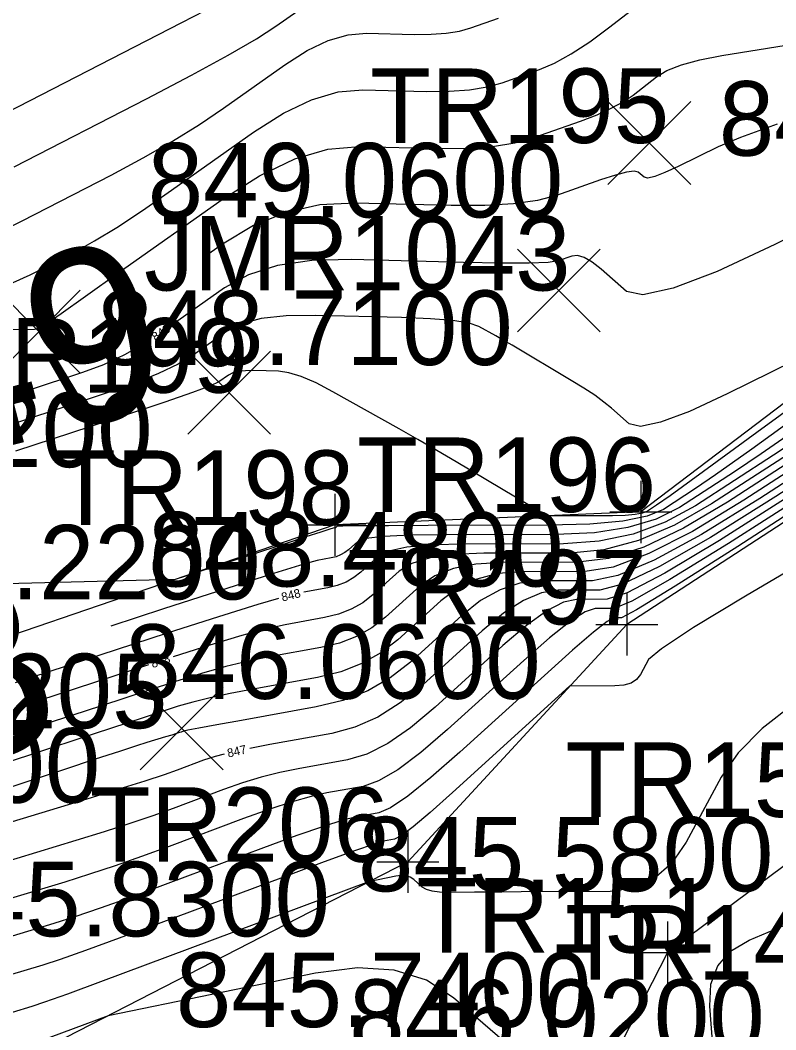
# Model space of a CAD drawing. Extents: x 1654928 to 1810050, y 486881 to 626330.
# Drawn here: x 1801367.8 to 1801379.97, y 489789.91 to 489806.17 of the extents above; entities that cross this region are included whole.
import ezdxf

# ---------------------------------------------------------------- set-up
doc = ezdxf.new("R2010")
doc.units = 0
for name, color, linetype in [('DR_X_Ditch', 7, 'Continuous'), ('DT_X_Contour_Major', 7, 'Continuous'), ('DT_X_Contour_Minor', 7, 'Continuous'), ('SV_X_Random_Point', 7, 'Continuous'), ('SV_X_Shot_Marker', 7, 'Continuous'), ('SV_X_Text_Elevation', 7, 'Continuous'), ('SV_X_Text_Name', 7, 'Continuous'), ('SV_X_Toe_of_Slope', 7, 'Continuous'), ('SV_X_Top_of_Bank', 7, 'Continuous')]:
    doc.layers.add(name, color=color, linetype=linetype)

msp = doc.modelspace()

# ---------------------------------------------------------------- linework, layer by layer
at = {"layer": 'DR_X_Ditch'}
msp.add_lwpolyline([(1801415.613, 489805.461), (1801399.12, 489798.656), (1801394.115, 489798.231), (1801381.169, 489793.34), (1801378.227, 489791.154), (1801376.864, 489788.486), (1801373.817, 489786.687), (1801350.547, 489785.463), (1801345.905, 489787.547), (1801327.981, 489787.847), (1801322.506, 489787.279)], dxfattribs=at)
at = {"layer": 'DT_X_Contour_Major'}
for points in [[(1801367.576, 489804.681), (1801370.403, 489806.138), (1801371.345, 489806.626)], [(1801379.993, 489804.497), (1801379.402, 489804.284), (1801379.044, 489804.134), (1801378.403, 489803.818), (1801378.188, 489803.718), (1801378.024, 489803.655), (1801377.912, 489803.63), (1801377.851, 489803.643), (1801377.756, 489803.726), (1801377.692, 489803.741), (1801377.57, 489803.725), (1801377.39, 489803.678), (1801377.152, 489803.599), (1801376.44, 489803.348), (1801376.134, 489803.267), (1801375.75, 489803.213), (1801375.287, 489803.187), (1801374.746, 489803.188), (1801373.199, 489803.228), (1801372.63, 489803.197), (1801372.084, 489803.076), (1801371.56, 489802.865), (1801371.059, 489802.563), (1801370.751, 489802.345)], [(1801382.452, 489800.238), (1801379.714, 489798.47), (1801378.776, 489797.89), (1801378.014, 489797.475), (1801377.429, 489797.226), (1801377.02, 489797.142), (1801376.166, 489797.14), (1801375.848, 489797.104), (1801375.532, 489796.998), (1801375.219, 489796.823), (1801374.909, 489796.578), (1801374.087, 489795.832), (1801373.76, 489795.577), (1801373.399, 489795.371), (1801373.001, 489795.216), (1801372.568, 489795.11), (1801371.365, 489794.894), (1801370.969, 489794.822), (1801370.681, 489794.769), (1801370.503, 489794.735), (1801370.434, 489794.721), (1801370.395, 489794.706), (1801370.369, 489794.697), (1801370.318, 489794.681), (1801370.242, 489794.658), (1801370.142, 489794.627), (1801369.844, 489794.536), (1801369.676, 489794.483), (1801369.399, 489794.394), (1801369.012, 489794.267), (1801368.514, 489794.103), (1801367.041, 489793.617)], [(1801380.363, 489799.623), (1801379.739, 489799.185), (1801379.309, 489798.896), (1801378.421, 489798.322), (1801378.047, 489798.134), (1801377.591, 489797.999), (1801377.053, 489797.917), (1801376.434, 489797.888), (1801374.671, 489797.883), (1801374.086, 489797.875), (1801373.652, 489797.854), (1801373.37, 489797.822), (1801373.238, 489797.778), (1801373.09, 489797.643), (1801373.031, 489797.597), (1801372.964, 489797.56), (1801372.891, 489797.531), (1801372.811, 489797.512), (1801372.586, 489797.472), (1801372.369, 489797.411), (1801371.883, 489797.261), (1801371.131, 489797.02), (1801370.111, 489796.689), (1801369.261, 489796.412)], [(1801380.633, 489797.57), (1801379.484, 489796.895), (1801378.65, 489796.388), (1801378.13, 489796.047), (1801377.923, 489795.873), (1801377.793, 489795.631), (1801377.73, 489795.552), (1801377.641, 489795.495), (1801377.525, 489795.46), (1801377.382, 489795.448), (1801376.652, 489795.443), (1801374.768, 489793.734), (1801374.407, 489793.412), (1801374.13, 489793.179), (1801373.938, 489793.034), (1801373.83, 489792.978), (1801373.655, 489792.947), (1801373.505, 489792.902), (1801373.187, 489792.791), (1801372.699, 489792.614), (1801372.044, 489792.371), (1801370.069, 489791.634), (1801369.395, 489791.384), (1801368.854, 489791.187), (1801368.445, 489791.044), (1801368.169, 489790.953), (1801367.609, 489790.783)]]:
    msp.add_lwpolyline(points, dxfattribs=at)
at = {"layer": 'DT_X_Contour_Minor'}
for points in [[(1801367.687, 489801.947), (1801367.965, 489802.071), (1801368.698, 489802.448), (1801369, 489802.616), (1801369.358, 489802.836), (1801369.771, 489803.109), (1801370.238, 489803.433), (1801371.56, 489804.369), (1801372.041, 489804.675), (1801372.495, 489804.891), (1801372.922, 489805.017), (1801373.321, 489805.052), (1801374.348, 489805.026), (1801374.713, 489805.027), (1801375.038, 489805.051), (1801375.323, 489805.097), (1801375.568, 489805.165), (1801376.169, 489805.378), (1801376.408, 489805.481), (1801376.677, 489805.63), (1801376.975, 489805.826), (1801377.301, 489806.068), (1801378.211, 489806.777)], [(1801367.706, 489803.811), (1801369.835, 489804.908), (1801370.564, 489805.289), (1801371.154, 489805.611), (1801371.607, 489805.874), (1801371.92, 489806.077), (1801372.573, 489806.539)], [(1801367.339, 489802.699), (1801367.835, 489802.941), (1801369.266, 489803.678), (1801369.782, 489803.953), (1801370.256, 489804.224), (1801370.689, 489804.491), (1801371.079, 489804.755), (1801372.066, 489805.454), (1801372.426, 489805.683), (1801372.765, 489805.844), (1801373.083, 489805.938), (1801373.381, 489805.964), (1801374.148, 489805.944), (1801374.421, 489805.945), (1801374.664, 489805.963), (1801374.877, 489805.997), (1801375.06, 489806.049), (1801375.508, 489806.207)], [(1801367.634, 489801.194), (1801367.881, 489801.193), (1801368.035, 489801.195), (1801368.095, 489801.2), (1801368.13, 489801.218), (1801368.46, 489801.448), (1801368.853, 489801.726), (1801369.397, 489802.112), (1801371.053, 489803.285), (1801371.657, 489803.668), (1801372.226, 489803.938), (1801372.76, 489804.096), (1801373.26, 489804.14), (1801374.547, 489804.107), (1801375.004, 489804.109), (1801375.412, 489804.138), (1801375.769, 489804.196), (1801376.076, 489804.282), (1801376.829, 489804.548), (1801377.094, 489804.649), (1801377.323, 489804.753), (1801377.516, 489804.858), (1801377.674, 489804.967), (1801378.049, 489805.258), (1801378.22, 489805.362), (1801378.454, 489805.454), (1801378.749, 489805.533), (1801379.106, 489805.602), (1801380.142, 489805.768)], [(1801382.74, 489803.929), (1801379.96, 489802.558), (1801379.029, 489802.126), (1801378.32, 489801.855), (1801377.833, 489801.747), (1801377.568, 489801.801), (1801377.159, 489802.16), (1801377.015, 489802.275), (1801376.888, 489802.348), (1801376.779, 489802.381), (1801376.687, 489802.372), (1801376.466, 489802.294), (1801376.309, 489802.27), (1801376.003, 489802.258), (1801375.549, 489802.258), (1801374.945, 489802.27), (1801373.138, 489802.316), (1801372.502, 489802.3), (1801371.949, 489802.219), (1801371.479, 489802.072), (1801371.091, 489801.86), (1801370.248, 489801.263)], [(1801382.372, 489801.721), (1801379.192, 489800.153), (1801378.582, 489799.871), (1801378.115, 489799.696), (1801377.793, 489799.63), (1801377.613, 489799.67), (1801377.326, 489799.923), (1801377.205, 489800.022), (1801377.056, 489800.13), (1801376.881, 489800.246), (1801376.678, 489800.37), (1801375.725, 489800.936), (1801375.579, 489801.02), (1801375.462, 489801.086), (1801375.187, 489801.24), (1801375.032, 489801.292), (1801374.773, 489801.333), (1801374.411, 489801.363), (1801373.945, 489801.382), (1801372.563, 489801.417), (1801372.085, 489801.411), (1801371.686, 489801.365), (1801371.365, 489801.281), (1801371.124, 489801.157), (1801370.586, 489800.776), (1801370.346, 489800.63), (1801370.03, 489800.479), (1801369.638, 489800.321), (1801369.17, 489800.158), (1801367.821, 489799.716), (1801367.371, 489799.572)], [(1801369.9, 489801.028), (1801369.824, 489800.978), (1801369.482, 489800.784), (1801369.144, 489800.623), (1801368.808, 489800.497), (1801367.916, 489800.205), (1801367.619, 489800.109)], [(1801380.853, 489800.396), (1801379.669, 489799.531), (1801378.808, 489798.904), (1801378.269, 489798.513), (1801378.052, 489798.358), (1801377.904, 489798.263), (1801377.827, 489798.231), (1801377.708, 489798.209), (1801377.545, 489798.195), (1801377.34, 489798.19), (1801376.284, 489798.187), (1801374.822, 489799.057), (1801374.512, 489799.24), (1801374.207, 489799.417), (1801373.908, 489799.589), (1801372.84, 489800.187), (1801372.567, 489800.329), (1801372.33, 489800.432), (1801372.128, 489800.495), (1801371.962, 489800.519), (1801371.568, 489800.529), (1801371.431, 489800.527), (1801371.317, 489800.514), (1801371.225, 489800.49), (1801371.156, 489800.455), (1801371.003, 489800.346), (1801370.868, 489800.282), (1801370.578, 489800.173), (1801370.133, 489800.019), (1801369.533, 489799.82), (1801367.726, 489799.228)], [(1801383.081, 489800.507), (1801379.973, 489798.5), (1801378.922, 489797.841), (1801378.099, 489797.371), (1801377.504, 489797.088), (1801377.138, 489796.993), (1801376.465, 489796.991), (1801376.2, 489796.95), (1801375.908, 489796.827), (1801375.589, 489796.623), (1801375.243, 489796.338), (1801374.286, 489795.469), (1801373.925, 489795.176), (1801373.561, 489794.947), (1801373.192, 489794.783), (1801372.82, 489794.684), (1801371.823, 489794.504), (1801371.5, 489794.443)], [(1801381.824, 489799.97), (1801379.456, 489798.441), (1801378.63, 489797.939), (1801377.929, 489797.58), (1801377.354, 489797.364), (1801376.903, 489797.291), (1801375.867, 489797.288), (1801375.495, 489797.258), (1801375.156, 489797.17), (1801374.849, 489797.023), (1801374.575, 489796.818), (1801373.887, 489796.194), (1801373.613, 489795.981), (1801373.306, 489795.808), (1801372.965, 489795.676), (1801372.592, 489795.586), (1801371.552, 489795.399), (1801371.184, 489795.329), (1801370.861, 489795.259), (1801370.583, 489795.19), (1801370.349, 489795.121), (1801369.784, 489794.936), (1801368.747, 489794.596), (1801368.224, 489794.423), (1801366.71, 489793.924)], [(1801380.425, 489799.871), (1801379.585, 489799.263), (1801379.004, 489798.849), (1801378.681, 489798.627), (1801378.163, 489798.292), (1801377.902, 489798.182), (1801377.507, 489798.103), (1801376.978, 489798.055), (1801376.316, 489798.037), (1801374.372, 489798.031), (1801373.734, 489798.029), (1801373.276, 489798.026), (1801373, 489798.022), (1801372.904, 489798.018), (1801372.891, 489798.005), (1801372.885, 489798.001), (1801372.879, 489797.998), (1801372.873, 489797.995), (1801372.865, 489797.993), (1801372.845, 489797.99), (1801372.791, 489797.973), (1801372.643, 489797.926), (1801372.403, 489797.848), (1801372.069, 489797.739), (1801370.296, 489797.161), (1801366.727, 489797.07)], [(1801381.195, 489799.701), (1801379.197, 489798.411), (1801378.484, 489797.988), (1801377.845, 489797.685), (1801377.279, 489797.502), (1801376.786, 489797.441), (1801375.568, 489797.437), (1801375.143, 489797.412), (1801374.78, 489797.341), (1801374.479, 489797.223), (1801374.241, 489797.058), (1801373.688, 489796.556), (1801373.467, 489796.385), (1801373.22, 489796.246), (1801372.947, 489796.14), (1801372.647, 489796.067), (1801371.811, 489795.917), (1801371.48, 489795.85), (1801371.117, 489795.76), (1801370.72, 489795.647), (1801370.289, 489795.513), (1801369.096, 489795.124), (1801368.649, 489794.978), (1801368.201, 489794.831), (1801368.18, 489794.824)], [(1801380.567, 489799.433), (1801378.938, 489798.381), (1801378.339, 489798.036), (1801377.76, 489797.789), (1801377.204, 489797.64), (1801376.668, 489797.59), (1801375.269, 489797.585), (1801374.791, 489797.566), (1801374.404, 489797.512), (1801374.109, 489797.422), (1801373.907, 489797.298), (1801373.489, 489796.919), (1801373.322, 489796.789), (1801373.135, 489796.684), (1801372.928, 489796.604), (1801372.701, 489796.549), (1801372.069, 489796.435), (1801371.776, 489796.37), (1801371.372, 489796.26), (1801370.857, 489796.105), (1801370.266, 489795.916)], [(1801380.474, 489799.521), (1801379.938, 489799.164), (1801378.68, 489798.352), (1801378.193, 489798.085), (1801377.676, 489797.894), (1801377.128, 489797.779), (1801376.551, 489797.739), (1801374.97, 489797.734), (1801374.438, 489797.72), (1801374.028, 489797.683), (1801373.739, 489797.622), (1801373.572, 489797.538), (1801373.289, 489797.281), (1801373.176, 489797.193), (1801373.05, 489797.122), (1801372.91, 489797.068), (1801372.756, 489797.03), (1801372.371, 489796.961)], [(1801380.749, 489798.589), (1801379.359, 489797.695), (1801378.352, 489797.057), (1801377.729, 489796.674), (1801377.49, 489796.546), (1801377.362, 489796.545), (1801377.257, 489796.487), (1801377.036, 489796.313), (1801376.699, 489796.024), (1801376.246, 489795.618), (1801374.884, 489794.383), (1801374.419, 489793.974), (1801374.047, 489793.675), (1801373.766, 489793.485), (1801373.577, 489793.405), (1801373.197, 489793.336), (1801372.998, 489793.286), (1801372.686, 489793.187), (1801372.26, 489793.038), (1801371.722, 489792.841), (1801370.135, 489792.248), (1801369.577, 489792.042), (1801369.092, 489791.869), (1801368.682, 489791.729), (1801368.346, 489791.622), (1801367.548, 489791.378)], [(1801380.232, 489798.53), (1801379.067, 489797.793), (1801378.183, 489797.266), (1801377.579, 489796.95), (1801377.255, 489796.844), (1801376.764, 489796.843), (1801376.552, 489796.796), (1801376.284, 489796.656), (1801375.959, 489796.423), (1801375.577, 489796.098), (1801374.485, 489795.107), (1801374.09, 489794.775), (1801373.723, 489794.523), (1801373.384, 489794.35), (1801373.073, 489794.257), (1801372.281, 489794.115), (1801371.983, 489794.054), (1801371.684, 489793.978), (1801371.382, 489793.887), (1801371.078, 489793.781), (1801370.265, 489793.477), (1801369.939, 489793.359), (1801369.569, 489793.234), (1801369.156, 489793.1), (1801368.7, 489792.958), (1801367.426, 489792.57)], [(1801380.49, 489798.559), (1801379.213, 489797.744), (1801378.268, 489797.161), (1801377.654, 489796.812), (1801377.372, 489796.695), (1801377.063, 489796.694), (1801376.905, 489796.641), (1801376.66, 489796.485), (1801376.329, 489796.224), (1801375.912, 489795.858), (1801374.685, 489794.745), (1801374.255, 489794.375), (1801373.885, 489794.099), (1801373.575, 489793.918), (1801373.325, 489793.831), (1801372.739, 489793.726), (1801372.491, 489793.67), (1801372.185, 489793.582), (1801371.821, 489793.463), (1801371.4, 489793.311), (1801370.2, 489792.863), (1801369.758, 489792.701), (1801369.331, 489792.552), (1801368.919, 489792.415), (1801368.523, 489792.29), (1801367.487, 489791.974)], [(1801371.964, 489796.859), (1801371.628, 489796.76), (1801370.994, 489796.563), (1801370.17, 489796.297), (1801367.722, 489795.499)], [(1801369.867, 489795.787), (1801368.409, 489795.311), (1801367.771, 489795.103)], [(1801380.263, 489795.159), (1801379.756, 489794.764), (1801379.367, 489794.37), (1801379.095, 489793.977), (1801378.529, 489792.93), (1801378.293, 489792.587), (1801378.01, 489792.34), (1801377.681, 489792.192), (1801377.304, 489792.14), (1801375.869, 489792.131), (1801375.559, 489792.129), (1801375.122, 489792.126), (1801374.7, 489792.123), (1801374.554, 489792.127), (1801374.436, 489792.143), (1801374.344, 489792.171), (1801374.279, 489792.21), (1801374.141, 489792.33), (1801374.084, 489792.367), (1801374.016, 489792.388), (1801373.939, 489792.393), (1801373.85, 489792.382), (1801373.415, 489792.293), (1801369.093, 489790.68), (1801368.562, 489790.485), (1801368.195, 489790.353), (1801367.992, 489790.285), (1801367.671, 489790.187)], [(1801371.09, 489794.35), (1801370.942, 489794.311), (1801370.756, 489794.251), (1801370.33, 489794.092), (1801370.12, 489794.018), (1801369.807, 489793.916), (1801369.393, 489793.785), (1801368.877, 489793.627), (1801367.364, 489793.166)], [(1801379.032, 489788.659), (1801378.909, 489790.293), (1801378.927, 489790.647), (1801379.039, 489790.942), (1801379.244, 489791.177), (1801379.542, 489791.352), (1801380.464, 489791.74)], [(1801375.843, 489789.506), (1801374.783, 489790.427), (1801374.345, 489790.711), (1801373.828, 489790.871), (1801373.233, 489790.909), (1801372.557, 489790.823), (1801369.221, 489790.137), (1801368.281, 489789.786)]]:
    msp.add_lwpolyline(points, dxfattribs=at)
at = {"layer": 'SV_X_Random_Point'}
for p, q in [((1801377.269, 489803.528), (1801378.602, 489804.863)), ((1801377.269, 489804.863), (1801378.602, 489803.528)), ((1801375.811, 489801.152), (1801377.145, 489802.487)), ((1801375.811, 489802.487), (1801377.145, 489801.152)), ((1801367.434, 489800.489), (1801368.768, 489801.824)), ((1801367.434, 489801.824), (1801368.768, 489800.489)), ((1801370.503, 489799.506), (1801371.836, 489800.841)), ((1801370.503, 489800.841), (1801371.836, 489799.506)), ((1801369.735, 489794.1), (1801371.069, 489795.435)), ((1801369.735, 489795.435), (1801371.069, 489794.1))]:
    msp.add_line(p, q, dxfattribs=at)
at = {"layer": 'SV_X_Shot_Marker'}
for p, q in [((1801377.801, 489798.751), (1801377.801, 489797.751)), ((1801372.871, 489798.542), (1801372.871, 489797.542)), ((1801377.301, 489798.251), (1801378.301, 489798.251)), ((1801377.801, 489798.251), (1801377.801, 489798.251)), ((1801372.371, 489798.042), (1801373.371, 489798.042)), ((1801372.871, 489798.042), (1801372.871, 489798.042)), ((1801377.572, 489796.941), (1801377.572, 489795.941)), ((1801377.072, 489796.441), (1801378.072, 489796.441)), ((1801377.572, 489796.441), (1801377.572, 489796.441)), ((1801374.044, 489793.116), (1801374.044, 489792.116)), ((1801373.544, 489792.616), (1801374.544, 489792.616)), ((1801374.044, 489792.616), (1801374.044, 489792.616)), ((1801378.227, 489791.654), (1801378.227, 489790.654)), ((1801377.727, 489791.154), (1801378.727, 489791.154)), ((1801378.227, 489791.154), (1801378.227, 489791.154))]:
    msp.add_line(p, q, dxfattribs=at)
at = {"layer": 'SV_X_Toe_of_Slope'}
msp.add_lwpolyline([(1801412.543, 489809.732), (1801392.991, 489804.275), (1801388.448, 489803.512), (1801377.572, 489796.441), (1801374.044, 489792.616), (1801367.753, 489789.382), (1801359.258, 489788.44), (1801349.57, 489789.663), (1801346.148, 489791.559), (1801338.511, 489793.341), (1801330.855, 489793.994), (1801326.103, 489791.66), (1801319.382, 489791.876), (1801317.575, 489794.338), (1801316.785, 489794.599)], dxfattribs=at)
at = {"layer": 'SV_X_Top_of_Bank'}
msp.add_lwpolyline([(1801422.074, 489809.374), (1801419.071, 489811.095), (1801415.847, 489811.951), (1801411.348, 489810.567), (1801392.1, 489806.2), (1801386.944, 489805.19), (1801377.801, 489798.251), (1801372.871, 489798.042), (1801363.859, 489794.96), (1801356.721, 489793.409), (1801350.319, 489794.339), (1801339.193, 489795.613), (1801330.88, 489795.172), (1801318.326, 489796.108)], dxfattribs=at)

# ---------------------------------------------------------------- texts
at = {"layer": 'DT_X_Contour_Major'}
for s, rotation, p in [('849', 14.4598, (1801364.287, 489798.454)), ('848', 17.0117, (1801362.611, 489792.833))]:
    msp.add_text(s, height=2.8, rotation=rotation, dxfattribs=at).set_placement(p)
at = {"layer": 'DT_X_Contour_Minor'}
for s, rotation, p in [('849', 33.9376, (1801369.981, 489800.997)), ('848', 14.1049, (1801372.028, 489796.807)), ('848', 18.0239, (1801369.935, 489795.735)), ('847', 18.243, (1801367.851, 489794.642)), ('847', 12.7812, (1801371.154, 489794.295))]:
    msp.add_text(s, height=0.14, rotation=rotation, dxfattribs=at).set_placement(p)
at = {"layer": 'SV_X_Text_Elevation'}
for s, p in [('848.7200', (1801379.055, 489803.99)), ('849.0600', (1801369.857, 489802.995)), ('848.7100', (1801369.043, 489800.619)), ('848.3200', (1801363.242, 489798.973)), ('848.4800', (1801369.864, 489797.051)), ('848.2200', (1801364.981, 489796.842)), ('846.0600', (1801369.494, 489795.241)), ('847.0200', (1801362.399, 489793.568)), ('845.5800', (1801373.242, 489792.14)), ('845.8300', (1801366.099, 489791.416)), ('845.7400', (1801370.309, 489789.954)), ('846.0200', (1801373.101, 489789.52))]:
    msp.add_text(s, height=1.2, dxfattribs=at).set_placement(p)
at = {"layer": 'SV_X_Text_Name'}
for s, p in [('TR195', (1801373.439, 489804.195)), ('JMR1043', (1801369.799, 489801.819)), ('TR199', (1801366.663, 489800.173)), ('TR196', (1801373.228, 489798.251)), ('TR198', (1801368.365, 489798.042)), ('TR197', (1801373.075, 489796.441)), ('TR205', (1801365.357, 489794.768)), ('TR150', (1801376.587, 489793.34)), ('TR206', (1801368.924, 489792.616)), ('TR151', (1801374.183, 489791.154)), ('TR146', (1801376.578, 489790.72))]:
    msp.add_text(s, height=1.2, dxfattribs=at).set_placement(p)

doc.saveas('drawing.dxf')
